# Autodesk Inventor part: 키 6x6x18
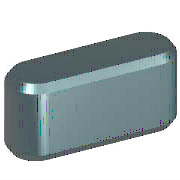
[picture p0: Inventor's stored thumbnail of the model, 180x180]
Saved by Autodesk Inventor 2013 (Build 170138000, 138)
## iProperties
IsCustomPart: 0
Created: 2012-02
Part Number: 키 6x6x18
Material: 강철, 연강
Document SubType Name: Modeling
Standard: JIS B 1301
Designer: mdu
Standards Organization: JIS
Language: ko-KR
Size Designation: 6x6x18
Categories: <MemberInstance><Categories><Category DisplayName="샤프트 부품" InternalName="7f7aeb1f-a693-4053-b835-cee3144e0d98" Mnemonic="SHFT"><Category DisplayName="키" Interna
Density: 1 g/cm^3
Author: mdu
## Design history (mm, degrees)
workplane "Work Plane1"
workplane "Work Plane2"
sketch "스케치1"
  geometry: L1 (3, 3)-(15, 3); L2 (15, -3)-(3, -3); L3 (0, 9.4)-(0, -7.4) reference; L4 (-5, 0)-(30, 0) reference; L5 (18, 0)-(18, 7); A1 r 3 centre (3, 0) between (3, 3) and (3, -3); A2 r 3 centre (15, 0) between (15, -3) and (15, 3)
  constraints: 6 end point, 5 point on circle, 4 tangent, 3 point on line, 2 centre point, 1 horizontal, 1 parallel, 1 perpendicular
  dimensions: "d0" = 3 radius of A1 (= 0.5 x PB); "d13" = 3 radius of A2 (= 0.5 x PB); "d14" = 18 distance between parallel lines of L5 L3 (= NLG)
extrude "본체1" new body sketch "스케치1" taper "d3" = 0 deg; stored distance "d4" = 10
workplane "Work Plane3"
body "Solid1"
chamfer "모따기1" distance "d8" = 0.4 (= PHH); stored, may be unused: second distance "d9" = 0.4 (= PHH), angle "d15" = 45 deg
other parameters: "d1" = -3.5 (= -PNT), "d2" = 2.5 (= PH - PNT), "NLG" = 18 [user parameter; used in 3 equation terms], "PB" = 6 [user parameter; used in 2 equation terms], "PNT" = 3.5 [user parameter; used in 2 equation terms], "PH" = 6 [user parameter; used in 1 equation term], "PHH" = 0.4 [user parameter; used in 2 equation terms], "d10" = 0, "d16" = 0, "d17" = 0, "d18" = 0, "WDMIN" = 17 [user parameter], "PLB2" = 18 (= NLG) [user parameter], "WDMAX" = 22 [user parameter], "PLB1" = 18 (= NLG) [user parameter], "RR" = 0.16 [user parameter], "PUEB" = 2.8 [user parameter]
